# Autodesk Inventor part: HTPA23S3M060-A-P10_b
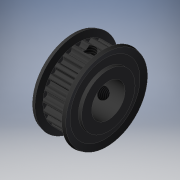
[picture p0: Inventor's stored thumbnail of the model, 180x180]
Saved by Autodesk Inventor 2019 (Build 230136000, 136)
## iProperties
Created: 2022-11
Part Number: HTPA23S3M060-A-P10_b
Material: Generic
Catalog Web Link: www.cadenas.de
Description: HTPA__S3M060, HTPA__S3M100, HTPA__S3M150, HTPB__S3M060, HTPB__S3M100, HTPB__S3M150, HTPK__S3M060, HTPK__S3M100, HTPK__S3M150, HTPN__S3M060, HTPN__S3M100, HTPN__
Vendor: MISUMI
Document SubType Name: Modeling
Designer: psAdmin
Manufacturer: MISUMI
Mass: 2.63016 g
Surface Area: 24.7129 cm^2
Volume: 2.63016 cm^3
Density: 1 g/cm^3
Appearance: PSOLRGB-175-175-175
Category: PARTsolutions
Company: MISUMI
Title: HTPA23S3M060-A-P10
Author: Cadenas PARTsolutions
Comments: High Torque Timing Pulleys S3M Type
PSOL_IDENT_0: {$CADENAS_DATA/23d-libs/misumi/metric/51_timing_pulleys/htpk_s3m/htpa_s3m.prj},837 {VTYP=3D},{NB=HTP
PSOL_IDENT_1: A23S3M060-A-P10_b},{LINA=HTPA23S3M060-A-P10},{NN=HTPA__S3M060, HTPA__S3M100, HTPA__S3M150, HTPB__S3M
PSOL_IDENT_2: 060, HTPB__S3M100, HTPB__S3M150, HTPK__S3M060, HTPK__S3M100, HTPK__S3M150, HTPN__S3M060, HTPN__S3M10
PSOL_IDENT_3: 0, HTPN__S3M150, HTPT__S3M060, HTPT__S3M100, HTPT__S3M150, HTPM__S3M060, HTPM__S3M100, HTPM__S3M150,
PSOL_IDENT_4: HTPP__S3M060, HTPP__S3M100, HTPP__S3M150, HTPS__S3M060, HTPS__S3M100, KHTPA__S3M060, KHTPA__S3M100,
PSOL_IDENT_5: KHTPA__S3M150, KHTPK__S3M060, KHTPK__S3M100, KHTPK__S3M150_body},{DATE=28.10.2022 00:10:57},{GEOMDA
PSOL_IDENT_6: TE=11.11.2021 09:52:43},{VERSION=},{LINEID=330},{WBVAR=MATP,ST,TNW,PS,SBS,DD,Z,J,Q,R,S,T,ALT1,ALT2,M
PSOL_IDENT_7: ,QSC,QFC,QTC,ALT3,K,KSC,KFC,KTC,ALT4,ZM,ZSC,ZFC,ZTC,ALT5,ALT6,ALT7,FC,ALT8,SRG,ALT9,BTC,TL,ALT10,TPC
PSOL_IDENT_8: ,ALT11,BC,ALT12,SLH,ALT13,BN},{WBNUMERIC=DD,Z,J,Q,R,S,T,QSC,QFC,QTC,K,KSC,KFC,KTC,ZSC,ZFC,ZTC,FC,SRG
PSOL_IDENT_9: ,BTC,TL,BC,SLH,BN}  {NB=HTPA23S3M060-A-P10_b},{LINA=HTPA23S3M060-A-P10},{KT=DUMMY},{PN=HTPA23S3M060-
PSOL_IDENT_10: A-P10},{TYPE=HTPA},{MATP=A2017},{MATPALG='A2017','Aluminum Alloy 2000 series','S45C','1045 Carbon St
PSOL_IDENT_11: eel Equivalent','SUS304','304 Stainless Steel','A6000','6000 Series Aluminum Alloy'},{ST=CA},{STALG=
PSOL_IDENT_12: 'CA','Clear Anodize','BA','Black Anodize','HAT','Hard Clear Anodize','ENP','Electroless Nickel Plat
PSOL_IDENT_13: ing' },{NT=23},{TNW=S3M060},{TNWALG= 'S3M060','S3M100','S3M150'    },{BW=6},{PS=A},{PSALG='A','B'},{
PSOL_IDENT_14: SBS=P},{SBSALG= 'H','Round Hole','P','Round Hole + Tap','V','Stepped Hole', 'Y','Both Ends Stepped H
PSOL_IDENT_15: ole','WB', 'Double Stepped Hole' },{SHSA= 'H','Round Hole','P','Round Hole + Tap','V','Stepped Hole'
PSOL_IDENT_16: , 'Y','Both Ends Stepped Hole','WB', 'Double Stepped Hole' },{SHSB= 'H','Round Hole','P','Round Hole
PSOL_IDENT_17: + Tap','V','Stepped Hole','F','Stepped Hole (Counterbore holes on the boss side)'},{SHSK='H','Round
PSOL_IDENT_18: Hole','P','Round Hole + Tap'},{SBSPN=-P10},{DD=10.00},{DDALG=[4:4/1],4.5,[5:6/1],6.35,[7:10/1]},{DD
PSOL_IDENT_19: HA=[4:4/1],4.5,[5:6/1],6.35,[7:12/1]},{DDHBK=0},{DDPA=[4:4/1],4.5,[5:6/1],6.35,[7:10/1]},{DDPBK=0},{
PSOL_IDENT_20: DDNA=[8:8/1],[10:11/1]},{DDNBK=0},{DDNK=0},{DDCA=[10:10/1]},{DDCBK=0},{DDVA=[4:4/1],4.5,[5:6/1],6.35
PSOL_IDENT_21: ,[7:10/1]},{DDVF=[4:4/1],4.5,[5:6/1],6.35,[7:8/1]},{DDY=[4:10/1]},{DDWB=[4:8/1]},{Z=0},{ZALG=[0]},{Z
PSOL_IDENT_22: QRMIN=12},{ZAMAX=12},{ZBMAX=10},{DDZ=10},{J=0.0},{JALG=[0]},{JMAX=9},{JMIN=2},{JPN=},{QRMAX=12},{QRM
PSOL_IDENT_23: IN=12},{WBRMAX=-2.00},{WBQMIN=14},{Q=0},{QALG=[0]},{QPN=},{R=0},{RALG=[0]},{S=0.0},{SALG=[0]},{SPN=}
PSOL_IDENT_24: ,{SMAX=5},{T=0.0},{TALG=[0]},{TPN=},{TMAX=8},{A=7},{W=11},{L=0},{PD=21.96},{OD=21.20},{D=0},{DALG=25
PSOL_IDENT_25: },{DE=16},{F=25},{E=16},{BBK=0.000},{TTK=0.0},{TT=1},{ANG=125.217391},{WL=11},{ALT1=},{ALT1ALG= '','
PSOL_IDENT_26: w/o KC90 (Set Screw Angle)','KC90','with KC90 (Set Screw Angle)' },{ALT1PN=},{ALT2=},{ALT2ALG= '','N
PSOL_IDENT_27: ot applicable' },{M=N/A},{MALG= 'N/A' },{MFTALG= 'N/A' },{MSALG= 'N/A' },{M3D=0.000},{KDML=0},{ML=0}
PSOL_IDENT_28: ,{MUL=0},{PITCH=0},{QSC=0.0},{QSCALG=0},{QFC=0.0},{QFCALG=0},{QTC=0.0},{QTCALG=0},{QPCDMIN=0},{QPCDM
PSOL_IDENT_29: INALG=0},{QPCDMAX=12},{ALT2PN=},{ALT3=},{ALT3ALG= '','Not applicable' },{K=0.0},{KALG=0},{KMIN=4},{K
PSOL_IDENT_30: FTMAX=0.0},{KSMAX=0.0},{KSC=0.0},{KSCALG=0},{KFC=0.0},{KFCALG=0},{KTC=0.0},{KTCALG=0},{KPCDMIN=14},{
PSOL_IDENT_31: KPCDMINALG=14},{KPCDMAX=12},{KSCMIN=14.0},{KSCMINALG=14},{ALT3PN=},{ALT4=},{ALT4ALG= '','Not applica
PSOL_IDENT_32: ble' },{ALT4MIN=20.5},{ALT4MAX=5.5},{ZM=N/A},{ZMALG= 'N/A' },{ZMSALG= 'N/A' },{ZMFTALG= 'N/A' },{ZMD
PSOL_IDENT_33: D1=0.0},{ZMDD2=0.0},{ZMHH=0.0},{ZSC=0.0},{ZSCALG=[0]},{ZFC=0.0},{ZFCALG=[0]},{ZTC=0.0},{ZTCALG=[0]},
PSOL_IDENT_34: {ZPCDMIN=0},{ZPCDMINALG=0},{ZPCDMAX=12},{ALT4PN=},{ALT5=},{ALT5ALG= '','Flange Attached','NFC','with
PSOL_IDENT_35: NFC (Flange not Attached)' },{ALT5PN=},{ALT6=},{ALT6ALG= '','w/o Flange Attached on One Side Only','
PSOL_IDENT_36: RFC','with RFC (Flange Attached on The Boss Side Only)','LFC','with LFC (Flange Attached on The Oppo
PSOL_IDENT_37: site Side Only)' },{ALT6PN=},{ALT7=},{ALT7ALG= '','w/o FC (Flange Cut)','FC','with FC (Flange Cut)'
PSOL_IDENT_38: },{FC=0.0},{FCALG=0},{FCMIN=22.5},{FCMAX=23.0},{ALT7PN=},{ALT8=},{ALT8ALG= '','Not applicable' },{AL
PSOL_IDENT_39: T8ALGALG=12},{ALT8DD2=0},{ALT8MM=0},{ALT8NN=0},{QC=0},{KC=0},{ZC=0},{SRG=0.0},{SRGALG=[0]},{SRGMAX1=
PSOL_IDENT_40: 0},{SRGMAX=0},{DD2=0.0},{MM=0.00},{NN=0.00},{ALT8PN=},{ALT9ALG= '','w/o BTC (Taper for Bearing Holde
PSOL_IDENT_41: r)','BTC','with BTC (Taper for Bearing Holder)' },{ALT9=},{BTC9=11},{TL9=1},{BTC=0},{BTCALG=[0]},{TL=
PSOL_IDENT_42: 0.0},{TLALG=0},{TLMIN=1.0},{TLMAX=-11.5},{BTCL=0},{BTCD=0},{BTCDALG=16.000},{ALT9PN=},{WLBCTL=11},{A
PSOL_IDENT_43: LT10=},{ALT10ALG= '','w/o TPC (Tapped Hole Dimension)','TPC','with TPC (Tapped Hole Dimension)' },{T
PSOL_IDENT_44: PC=N/A},{TPCALG= 'N/A' },{TPCM=4},{ALT10PN=},{ALT11=},{ALT11ALG= '','Not applicable' },{BC=0.0},{BCA
PSOL_IDENT_45: LG=0},{BCMIN=7},{BCMAX=-11.5},{BCPLANE=5.5},{M1WBC=5.5},{ALT11PN=},{ALT12=},{ALT12ALG= '','w/o SLH (
PSOL_IDENT_46: Set Screw Length)','SLH','with SLH (Set Screw Length)' },{SLH=0},{SLHALG=[0]},{ALT12PN=},{AC=M4x3},{
PSOL_IDENT_47: M1=4},{M1L=3},{TAP=0.000},{KYY=5},{KTT=5.6},{PLANE=11},{CD=0},{ALT13=},{ALT13ALG= '', 'Not applicabl
PSOL_IDENT_48: e' },{BN=0.0},{BNALG=0},{BNMIN=-10.5},{BNMAX=-1.0},{ALT13PN=}
NB: HTPA23S3M060-A-P10_b
NN: 0
NT: 23
NBSYN: $PN._b
LINA: HTPA23S3M060-A-P10
CATALOG: Misumi
PN: HTPA23S3M060-A-P10
MATP: Aluminum Alloy 2000 series
ST: Clear Anodize
TNW: S3M060
BW: 6
PS: A
SBS: Round Hole + Tap
DD: 10
Z: 0
J: 0
Q: 0
R: 0
S: 0
T: 0
A: 7
W: 11
L: 0
PD: 21.96
OD: 21.2
D: 0
F: 25
E: 16
TT: 1
ALT1: w/o KC90 (Set Screw Angle)
ALT2: Not applicable
M: N/A
QSC: 0
QFC: 0
QTC: 0
ALT3: Not applicable
K: 0
KSC: 0
KFC: 0
KTC: 0
ALT4: Not applicable
ZM: N/A
ZMDD1: 0
ZMDD2: 0
ZMHH: 0
ZSC: 0
ZFC: 0
ZTC: 0
ALT5: Flange Attached
ALT6: w/o Flange Attached on One Side Only
ALT7: w/o FC (Flange Cut)
FC: 0
ALT8: Not applicable
SRG: 0
DD2: 0
MM: 0
ALT9: w/o BTC (Taper for Bearing Holder)
BTC: 0
TL: 0
BTCL: 0
BTCD: 0
ALT10: w/o TPC (Tapped Hole Dimension)
TPC: N/A
ALT11: Not applicable
BC: 0
ALT12: w/o SLH (Set Screw Length)
SLH: 0
AC: M4x3
ALT13: Not applicable
BN: 0
SUPPLIER: MISUMI
ARTICLENO: HTPA23S3M060-A-P10_b
BOMINFO: HTPA23S3M060-A-P10
CREATOR: CADENAS GmbH
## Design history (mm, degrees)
sketch "_____1"
  geometry: L1 (11, 0)-(0, 0); L2 (0, 0)-(0, 8); L3 (0, 8)-(1, 8); L4 (1, 8)-(1, 10.468); L5 (1, 10.468)-(0.525, 12.241); L6 (0.525, 12.241)-(1.491, 12.5); L7 (1.491, 12.5)-(2, 10.6); L8 (2, 10.6)-(9, 10.6); L9 (9, 10.6)-(9.509, 12.5); L10 (9.509, 12.5)-(10.475, 12.241); L11 (10.475, 12.241)-(10, 10.468); L12 (10, 10.468)-(10, 8); L13 (10, 8)-(11, 8); L14 (11, 8)-(11, 0); L15 (11, 0)-(0, 0)
  constraints: 30 end point
revolve "Revolution1" sketch "_____1" stored, may be unused: angle "d0" = 360 deg
sketch "Sketch2"
  geometry: 1 further point
hole "Hole1" sketch "Sketch2" at (0, 0) diameter "d1" = 10; stored, may be unused: countersink angle "d5" = 90 deg, drill point angle "d7" = 0 deg; dims "d2" = 6, "d3" = 4, "d4" = 2, "d6" = 11
sketch "_____6"
  geometry: C1 r 15.6 at (0, 0); A1 r 0.28 centre (-10.309, 0.471) between (-10.589, 0.484) and (-10.376, 0.199); A2 r 1.975 centre (-10.845, -1.719) between (-9.534, -0.242) and (-10.376, 0.199); A3 r 0.15 centre (-9.634, -0.354) between (-9.484, -0.348) and (-9.534, -0.242); A4 r 9.49 centre (0, 0) between (-9.484, -0.348) and (-9.443, -0.946); A5 r 0.15 centre (-9.592, -0.961) between (-9.478, -1.059) and (-9.443, -0.946); A6 r 1.975 centre (-10.978, 0.226) between (-10.252, -1.61) and (-9.478, -1.059); A7 r 0.28 centre (-10.149, -1.871) between (-10.252, -1.61) and (-10.424, -1.922); A8 r 10.6 centre (0, 0) between (-10.424, -1.922) and (-10.327, -2.391); A9 r 0.28 centre (-10.054, -2.327) between (-10.327, -2.391) and (-10.045, -2.607); A10 r 1.975 centre (-9.979, -4.581) between (-9.115, -2.805) and (-10.045, -2.607); A11 r 0.15 centre (-9.181, -2.94) between (-9.038, -2.894) and (-9.115, -2.805); A12 r 9.49 centre (0, 0) between (-9.038, -2.894) and (-8.837, -3.459); A13 r 0.15 centre (-8.977, -3.513) between (-8.841, -3.577) and (-8.837, -3.459); A14 r 1.975 centre (-10.632, -2.744) between (-9.437, -4.317) and (-8.841, -3.577); A15 r 0.28 centre (-9.268, -4.54) between (-9.437, -4.317) and (-9.519, -4.663); A16 r 10.6 centre (0, 0) between (-9.519, -4.663) and (-9.299, -5.088); A17 r 0.28 centre (-9.053, -4.954) between (-9.299, -5.088) and (-8.969, -5.221); A18 r 1.975 centre (-8.373, -7.103) between (-8.02, -5.16) and (-8.969, -5.221); A19 r 0.15 centre (-8.047, -5.308) between (-7.922, -5.225) and (-8.02, -5.16); A20 r 9.49 centre (0, 0) between (-7.922, -5.225) and (-7.576, -5.715); A21 r 0.15 centre (-7.696, -5.805) between (-7.548, -5.829) and (-7.576, -5.715); A22 r 1.975 centre (-9.497, -5.51) between (-7.923, -6.703) and (-7.548, -5.829); A23 r 0.28 centre (-7.699, -6.872) between (-7.923, -6.703) and (-7.908, -7.058); A24 r 10.6 centre (0, 0) between (-7.908, -7.058) and (-7.581, -7.408); A25 r 0.28 centre (-7.381, -7.213) between (-7.581, -7.408) and (-7.228, -7.447); A26 r 1.975 centre (-6.146, -9.099) between (-6.331, -7.133) and (-7.228, -7.447); A27 r 0.15 centre (-6.317, -7.282) between (-6.218, -7.169) and (-6.331, -7.133); A28 r 9.49 centre (0, 0) between (-6.218, -7.169) and (-5.754, -7.547); A29 r 0.15 centre (-5.845, -7.666) between (-5.695, -7.65) and (-5.754, -7.547); A30 r 1.975 centre (-7.658, -7.868) between (-5.821, -8.592) and (-5.695, -7.65); A31 r 0.28 centre (-5.56, -8.694) between (-5.821, -8.592) and (-5.711, -8.93); A32 r 10.6 centre (0, 0) between (-5.711, -8.93) and (-5.302, -9.179); A33 r 0.28 centre (-5.162, -8.937) between (-5.302, -9.179) and (-4.951, -9.121); A34 r 1.975 centre (-3.463, -10.42) between (-4.172, -8.576) and (-4.951, -9.121); A35 r 0.15 centre (-4.118, -8.716) between (-4.054, -8.581) and (-4.172, -8.576); A36 r 9.49 centre (0, 0) between (-4.054, -8.581) and (-3.504, -8.819); A37 r 0.15 centre (-3.559, -8.959) between (-3.42, -8.903) and (-3.504, -8.819); A38 r 1.975 centre (-5.251, -9.643) between (-3.287, -9.843) and (-3.42, -8.903); A39 r 0.28 centre (-3.008, -9.872) between (-3.287, -9.843) and (-3.09, -10.14); A40 r 10.6 centre (0, 0) between (-3.09, -10.14) and (-2.629, -10.269); A41 r 0.28 centre (-2.559, -9.998) between (-2.629, -10.269) and (-2.306, -10.118); A42 r 1.975 centre (-0.523, -10.968) between (-1.703, -9.384) and (-2.306, -10.118); A43 r 0.15 centre (-1.614, -9.504) between (-1.588, -9.356) and (-1.703, -9.384); A44 r 9.49 centre (0, 0) between (-1.588, -9.356) and (-0.995, -9.438); A45 r 0.15 centre (-1.01, -9.587) between (-0.892, -9.495) and (-0.995, -9.438); A46 r 1.975 centre (-2.455, -10.702) between (-0.509, -10.365) and (-0.892, -9.495); A47 r 0.28 centre (-0.233, -10.317) between (-0.509, -10.365) and (-0.239, -10.597); A48 r 10.6 centre (0, 0) between (-0.239, -10.597) and (0.239, -10.597); A49 r 0.28 centre (0.233, -10.317) between (0.239, -10.597) and (0.509, -10.365); A50 r 1.975 centre (2.455, -10.702) between (0.892, -9.495) and (0.509, -10.365); A51 r 0.15 centre (1.01, -9.587) between (0.995, -9.438) and (0.892, -9.495); A52 r 9.49 centre (0, 0) between (0.995, -9.438) and (1.588, -9.356); A53 r 0.15 centre (1.614, -9.504) between (1.703, -9.384) and (1.588, -9.356); A54 r 1.975 centre (0.523, -10.968) between (2.306, -10.118) and (1.703, -9.384); A55 r 0.28 centre (2.559, -9.998) between (2.306, -10.118) and (2.629, -10.269); A56 r 10.6 centre (0, 0) between (2.629, -10.269) and (3.09, -10.14); A57 r 0.28 centre (3.008, -9.872) between (3.09, -10.14) and (3.287, -9.843); A58 r 1.975 centre (5.251, -9.643) between (3.42, -8.903) and (3.287, -9.843); A59 r 0.15 centre (3.559, -8.959) between (3.504, -8.819) and (3.42, -8.903); A60 r 9.49 centre (0, 0) between (3.504, -8.819) and (4.054, -8.581); A61 r 0.15 centre (4.118, -8.716) between (4.172, -8.576) and (4.054, -8.581); A62 r 1.975 centre (3.463, -10.42) between (4.951, -9.121) and (4.172, -8.576); A63 r 0.28 centre (5.162, -8.937) between (4.951, -9.121) and (5.302, -9.179); A64 r 10.6 centre (0, 0) between (5.302, -9.179) and (5.711, -8.93)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; 1 further point
  constraints: 368 point on circle, 185 centre point
extrude "Extrusion1" cut sketch "_____6" distance "d8" = 7; taper "d9" = 0 deg
sketch "_____18"
  geometry: L1 (0, 0)-(0, 10.6); L2 (0, 10.6)-(1.621, 10.6); L3 (1.621, 10.6)-(1.621, 0); L4 (1.621, 0)-(0, 0); L5 (0, 0)-(0, 10.6)
  constraints: 10 end point
revolve "Revolution2" sketch "_____18" stored, may be unused: angle "d10" = 360 deg
thread "Thread1" dims "d11" = 5.6, "d12" = 0
sketch "_____19"
  geometry: L1 (0, 0)-(8.66, -6.113); L2 (8.66, -6.113)-(7.725, -7.437); L3 (7.725, -7.437)-(-0.935, -1.324); L4 (-0.935, -1.324)-(0, 0); L5 (0, 0)-(8.66, -6.113)
  constraints: 10 end point
revolve "Revolution3" sketch "_____19" stored, may be unused: angle "d13" = 360 deg
thread "Thread2" dims "d14" = 5.6, "d15" = 0.14538
node "to_belt_XY"
node "to_belt_YZ"
node "to_belt_ZX"
node "to_belt_X"
node "to_belt_Y"
node "to_belt_Z"
node "to_belt_Center"
node "to_screw1_XY"
node "to_screw1_YZ"
node "to_screw1_ZX"
node "to_screw1_X"
node "to_screw1_Y"
node "to_screw1_Z"
node "to_screw1_Center"
node "to_screw2_XY"
node "to_screw2_YZ"
node "to_screw2_ZX"
node "to_screw2_X"
node "to_screw2_Y"
node "to_screw2_Z"
node "to_screw2_Center"
body "Solid1"
